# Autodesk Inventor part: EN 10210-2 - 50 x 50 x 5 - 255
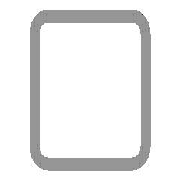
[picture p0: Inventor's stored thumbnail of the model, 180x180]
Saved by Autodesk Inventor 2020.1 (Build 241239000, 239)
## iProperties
_CCFamilyMember: 16
_CCFamilyDisplayName: DIN EN 10210-2 (USAS B17.1 quadratisch) - Rohrleitung — In Klammern angegebene Größen wurden aufgehoben
_FrameMemberDoc: Frame Member File
_Version: 15.0.0
_GetPNFromCC: 1
IsCustomPart: 1
Created: 2019-01
Part Number: EN 10210-2 - 50 x 50 x 5 - 255
Material: Stahl, weich
Description: Rohrleitung
Document SubType Name: Modeling
Standard: DIN
Designer: lutzd
Standard Revision: 2006-07
Standards Organization: DIN
Language: de-DE
Size Designation: 50 x 50 x 5
Categories: <MemberInstance><Categories><Category DisplayName="Profile" InternalName="089c4875-fa83-4c05-b084-43b9cc11f5ed" Mnemonic="GRDR"><CategoryParameter DisplayName="
Stock Number: 50 x 50 x 5
Mass: 1747.88 g
Surface Area: 880.74 cm^2
Volume: 222.66 cm^3
Density: 7.85 g/cm^3
Appearance: Halbpoliert
G_L: 255,000 mm
G_W: 50,000 mm
G_H: 50,000 mm
DocNumber: ADSK-014084
Folder: .
Dimensions: 50x50x255 mm
Mass: 1,748 kg
+DD56B6CD-BAFA-4945-BF69-EA339C8D9C0C+SCHNITTDETAIL1: Schnittwinkel 90,00 grd
+8269E6EE-F2AD-4244-926E-B4F1423BFF4B+SCHNITTDETAIL2: Schnittwinkel 90,00 grd
Title: Profil-Bauteil
Author: lutzd
Revision Number: -
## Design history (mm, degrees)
node "Startebene"
node "Endebene"
sketch "Skizze"
  geometry: L1 (-25, -17.5)-(-25, 17.5); L2 (-17.5, 25)-(17.5, 25); L3 (25, 17.5)-(25, -17.5); L4 (17.5, -25)-(-17.5, -25); L5 (-15, 20)-(15, 20); L6 (20, 15)-(20, -15); L7 (15, -20)-(-15, -20); L8 (-20, -15)-(-20, 15); L9 (0, 37.175)-(0, -37.175) reference; L10 (-37.175, 0)-(37.175, 0) reference; A1 r 7.5 centre (-17.5, -17.5) between (-25, -17.5) and (-17.5, -25); A2 r 7.5 centre (-17.5, 17.5) between (-17.5, 25) and (-25, 17.5); A3 r 7.5 centre (17.5, 17.5) between (25, 17.5) and (17.5, 25); A4 r 7.5 centre (17.5, -17.5) between (17.5, -25) and (25, -17.5); A5 r 5 centre (-15, -15) between (-20, -15) and (-15, -20); A6 r 5 centre (-15, 15) between (-15, 20) and (-20, 15); A7 r 5 centre (15, 15) between (20, 15) and (15, 20); A8 r 5 centre (15, -15) between (15, -20) and (20, -15)
  constraints: 16 end point, 16 point on circle, 16 tangent, 8 centre point, 6 equal radius, 4 parallel, 2 perpendicular, 2 other
  dimensions: "d7" = 7.5 radius of A1 (= G_IR); "d10" = 50 distance between parallel lines of L2 L4 (= G_H); "d11" = 50 distance between parallel lines of L1 L3 (= G_W); "d12" = 5 distance between parallel lines of L3 L6 (= G_T); "d15" = 25 distance between parallel lines of L2 L10 (= 0.5 x d10); "d16" = 25 distance between parallel lines of L9 L3 (= 0.5 x d11); "d19" = 5 radius of A5 (= G_T); "d20" = 5 distance between parallel lines of L4 L7 (= G_T)
extrude "Körper" new body sketch "Skizze" stored distance "d3" = 255 (= G_L); taper "d4" = 0 deg
node "Driven Length"
  sketch "Sketch3"
    geometry: L1 (0, 0)-(10, 0) reference
    constraints: 2 end point, 1 horizontal
  workplane "Work Plane3"
  sketch "Sketch4"
    geometry: L1 (-2, 50)-(12, 50) reference; L2 (-2, 305)-(12, 305) reference
    dimensions: "d18" = 255 distance between parallel lines of L1 L2 (derived)
workplane "Arbeitsebene4"
feature "Trennen1"
workplane "Arbeitsebene5"
feature "Trennen2"
body "Solid1"
other parameters: "G_W" = 50 [user parameter; used in 1 equation term], "G_H" = 50 [user parameter; used in 1 equation term], "G_T" = 5 [user parameter; used in 3 equation terms], "G_IR" = 7.5 [user parameter; used in 1 equation term], "G_L" = 255 (= d18) [user parameter; used in 1 equation term], "G_OFFSET_END" = -25 [user parameter; used in 1 equation term], "d14" = 305 (= G_OFFSET_END + B_L), "d17" = 90 deg
